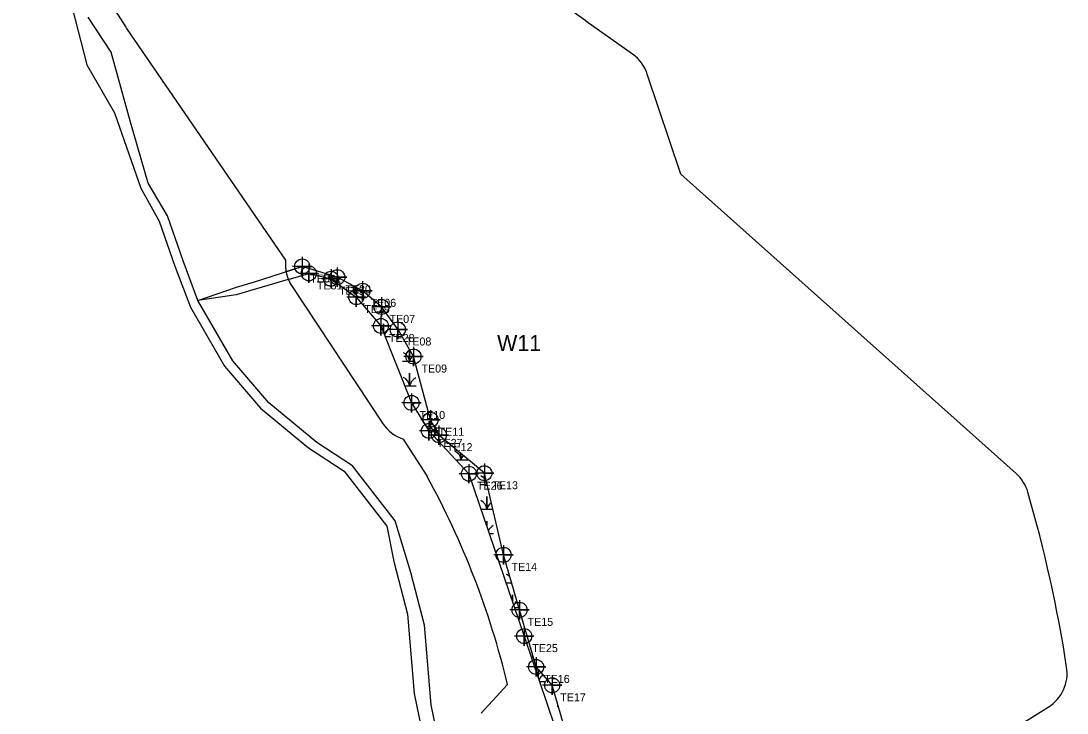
# Model space of a CAD drawing. Extents: x 1253697 to 1278588, y 912189 to 981699.
# Drawn here: x 1261524 to 1262831, y 929456 to 930320 of the extents above; entities that cross this region are included whole.
import ezdxf

# ---------------------------------------------------------------- set-up
doc = ezdxf.new("R2010")
doc.units = 0
for name, color, linetype in [('Default', 7, 'Continuous'), ('Exist Environmental Wetland Boundary', 7, 'Continuous'), ('Exist Environmental Wetland Boundary Cogo Comment', 7, 'Continuous'), ('Exist Environmental Wetland Boundary Cogo Number', 7, 'Continuous'), ('Exist Environmental Wetland Boundary Cogo Point CELL', 7, 'Continuous'), ('Exist Hydro Jurisdictional Stream or Body of Water Mitigable', 7, 'Continuous'), ('Exist Hydro Swamp or Marsh', 7, 'Continuous')]:
    doc.layers.add(name, color=color, linetype=linetype)

msp = doc.modelspace()

# ---------------------------------------------------------------- linework, layer by layer
at = {"layer": 'Default'}
for p, q in [((1261524.5, 930517.8), (1261655.6, 930312.4)), ((1261524.5, 930517.8), (1261655.6, 930312.4)), ((1261524.5, 930517.8), (1261655.6, 930312.4)), ((1261524.5, 930517.8), (1261655.6, 930312.4)), ((1262288.5, 930278.8), (1262230.3, 930320.2)), ((1262288.5, 930278.8), (1262230.3, 930320.2)), ((1262288.5, 930278.8), (1262230.3, 930320.2)), ((1262288.5, 930278.8), (1262230.3, 930320.2)), ((1261656.5, 930311), (1261855.1, 930021.6)), ((1261656.5, 930311), (1261855.1, 930021.6)), ((1261656.5, 930311), (1261855.1, 930021.6)), ((1261656.5, 930311), (1261855.1, 930021.6)), ((1261863.1, 929988.6), (1261976.2, 929817.7)), ((1261863.1, 929988.6), (1261976.2, 929817.7)), ((1261863.1, 929988.6), (1261976.2, 929817.7)), ((1261863.1, 929988.6), (1261976.2, 929817.7)), ((1262002.1, 929797.9), (1262031.6, 929751.8)), ((1262002.1, 929797.9), (1262031.6, 929751.8)), ((1262002.1, 929797.9), (1262031.6, 929751.8)), ((1262002.1, 929797.9), (1262031.6, 929751.8)), ((1262132.3, 929491.3), (1262099.5, 929455.5)), ((1262132.3, 929491.3), (1262099.5, 929455.5)), ((1262132.3, 929491.3), (1262099.5, 929455.5)), ((1262132.3, 929491.3), (1262099.5, 929455.5))]:
    msp.add_line(p, q, dxfattribs=at)
for points in [[(1262230.1, 930320.3), (1261823.6, 930606.2), (1261817.1, 930616.3), (1261806.6, 930645)], [(1262230.1, 930320.3), (1261823.6, 930606.2), (1261817.1, 930616.3), (1261806.6, 930645)], [(1262230.1, 930320.3), (1261823.6, 930606.2), (1261817.1, 930616.3), (1261806.6, 930645)], [(1262230.1, 930320.3), (1261823.6, 930606.2), (1261817.1, 930616.3), (1261806.6, 930645)], [(1262767.6, 929754.7), (1262349, 930128.9), (1262306.9, 930254)], [(1262767.6, 929754.7), (1262349, 930128.9), (1262306.9, 930254)], [(1262767.6, 929754.7), (1262349, 930128.9), (1262306.9, 930254)], [(1262767.6, 929754.7), (1262349, 930128.9), (1262306.9, 930254)], [(1262512, 929210.9), (1262495.3, 929268.1), (1262807.7, 929463)], [(1262512, 929210.9), (1262495.3, 929268.1), (1262807.7, 929463)], [(1262512, 929210.9), (1262495.3, 929268.1), (1262807.7, 929463)], [(1262512, 929210.9), (1262495.3, 929268.1), (1262807.7, 929463)]]:
    msp.add_lwpolyline(points, dxfattribs=at)
for centre, radius, start, end in [((1262201.4, 930279.4), 50, 54.5771, 54.8877), ((1262201.4, 930279.4), 50, 54.5771, 54.8877), ((1262201.4, 930279.4), 50, 54.5771, 54.8877), ((1262201.4, 930279.4), 50, 54.5771, 54.8877), ((1261697.7, 930339.3), 50, 212.5522, 214.4514), ((1261697.7, 930339.3), 50, 212.5522, 214.4514), ((1261697.7, 930339.3), 50, 212.5522, 214.4514), ((1261697.7, 930339.3), 50, 212.5522, 214.4514), ((1262259.5, 930238.1), 50, 18.5876, 54.5771), ((1262259.5, 930238.1), 50, 18.5876, 54.5771), ((1262259.5, 930238.1), 50, 18.5876, 54.5771), ((1262259.5, 930238.1), 50, 18.5876, 54.5771), ((1261904.8, 930016.2), 50, 173.8185, 213.5071), ((1261904.8, 930016.2), 50, 173.8185, 213.5071), ((1261904.8, 930016.2), 50, 173.8185, 213.5071), ((1261904.8, 930016.2), 50, 173.8185, 213.5071), ((1262017.9, 929845.3), 50, 213.5071, 251.5595), ((1262017.9, 929845.3), 50, 213.5071, 251.5595), ((1262017.9, 929845.3), 50, 213.5071, 251.5595), ((1262017.9, 929845.3), 50, 213.5071, 251.5595), ((1261111.3, 929246.3), 1050, 13.493, 28.7764), ((1261111.3, 929246.3), 1050, 13.493, 28.7764), ((1261111.3, 929246.3), 1050, 13.493, 28.7764), ((1261111.3, 929246.3), 1050, 13.493, 28.7764), ((1262734.3, 929717.5), 50, 16.1865, 48.2089), ((1262734.3, 929717.5), 50, 16.1865, 48.2089), ((1262734.3, 929717.5), 50, 16.1865, 48.2089), ((1262734.3, 929717.5), 50, 16.1865, 48.2089), ((1261111.3, 929246.3), 1740, 8.8188, 16.1865), ((1261111.3, 929246.3), 1740, 8.8188, 16.1865), ((1261111.3, 929246.3), 1740, 8.8188, 16.1865), ((1261111.3, 929246.3), 1740, 8.8188, 16.1865), ((1262781.3, 929505.4), 50, 301.9596, 8.8188), ((1262781.3, 929505.4), 50, 301.9596, 8.8188), ((1262781.3, 929505.4), 50, 301.9596, 8.8188), ((1262781.3, 929505.4), 50, 301.9596, 8.8188)]:
    msp.add_arc(centre, radius, start, end, dxfattribs=at)
at = {"layer": 'Exist Environmental Wetland Boundary'}
for points in [[(1261858.5, 929997.3), (1261793.3, 929978), (1261745.3, 929971.2), (1261793.9, 929987.8), (1261814.8, 929993.8), (1261875.9, 930013.5)], [(1262206.1, 929428.6), (1262188.1, 929490.2), (1262168, 929513.4), (1262147.3, 929584.5), (1262127.3, 929653.2), (1262103.4, 929755.2), (1262046.6, 929802.8), (1262036.2, 929822), (1262014.8, 929901), (1261996.2, 929934.1), (1261974.9, 929963), (1261951.3, 929983.1), (1261919.7, 930000.1), (1261875.9, 930013.5), (1261855.6, 930007)], [(1261858.5, 929997.3), (1261884.2, 930004.9), (1261911.9, 929998.1), (1261943.4, 929975.2), (1261974.2, 929939.2), (1262012.4, 929843), (1262034.2, 929808.1), (1262084.1, 929754.6), (1262153.2, 929551.7), (1262191.5, 929438.5)]]:
    msp.add_lwpolyline(points, dxfattribs=at)
at = {"layer": 'Exist Environmental Wetland Boundary Cogo Point CELL'}
for points in [[(1261875.9, 930025.5), (1261875.9, 930001.5), (1261875.9, 930013.5), (1261887.9, 930013.5), (1261863.9, 930013.5)], [(1261884.2, 930016.9), (1261884.2, 929992.9), (1261884.2, 930004.9), (1261896.2, 930004.9), (1261872.2, 930004.9)], [(1261911.9, 930010.1), (1261911.9, 929986.1), (1261911.9, 929998.1), (1261923.9, 929998.1), (1261899.9, 929998.1)], [(1261919.7, 930012.1), (1261919.7, 929988.1), (1261919.7, 930000.1), (1261931.7, 930000.1), (1261907.7, 930000.1)], [(1261951.3, 929995.1), (1261951.3, 929971.1), (1261951.3, 929983.1), (1261963.3, 929983.1), (1261939.3, 929983.1)], [(1261943.4, 929987.2), (1261943.4, 929963.2), (1261943.4, 929975.2), (1261955.4, 929975.2), (1261931.4, 929975.2)], [(1261974.9, 929975), (1261974.9, 929951), (1261974.9, 929963), (1261986.9, 929963), (1261962.9, 929963)], [(1261974.2, 929951.2), (1261974.2, 929927.2), (1261974.2, 929939.2), (1261986.2, 929939.2), (1261962.2, 929939.2)], [(1261995.2, 929946.8), (1261995.2, 929922.8), (1261995.2, 929934.8), (1262007.2, 929934.8), (1261983.2, 929934.8)], [(1262014.8, 929913), (1262014.8, 929889), (1262014.8, 929901), (1262026.8, 929901), (1262002.8, 929901)], [(1262012.4, 929855), (1262012.4, 929831), (1262012.4, 929843), (1262024.4, 929843), (1262000.4, 929843)], [(1262036.2, 929834), (1262036.2, 929810), (1262036.2, 929822), (1262048.2, 929822), (1262024.2, 929822)], [(1262034.2, 929820.1), (1262034.2, 929796.1), (1262034.2, 929808.1), (1262046.2, 929808.1), (1262022.2, 929808.1)], [(1262046.6, 929814.8), (1262046.6, 929790.8), (1262046.6, 929802.8), (1262058.6, 929802.8), (1262034.6, 929802.8)], [(1262084.1, 929766.6), (1262084.1, 929742.6), (1262084.1, 929754.6), (1262096.1, 929754.6), (1262072.1, 929754.6)], [(1262103.4, 929767.2), (1262103.4, 929743.2), (1262103.4, 929755.2), (1262115.4, 929755.2), (1262091.4, 929755.2)], [(1262127.3, 929665.2), (1262127.3, 929641.2), (1262127.3, 929653.2), (1262139.3, 929653.2), (1262115.3, 929653.2)], [(1262147.3, 929596.5), (1262147.3, 929572.5), (1262147.3, 929584.5), (1262159.3, 929584.5), (1262135.3, 929584.5)], [(1262153.2, 929563.7), (1262153.2, 929539.7), (1262153.2, 929551.7), (1262165.2, 929551.7), (1262141.2, 929551.7)], [(1262168, 929525.2), (1262168, 929501.2), (1262168, 929513.2), (1262180, 929513.2), (1262156, 929513.2)], [(1262188.1, 929502.3), (1262188.1, 929478.3), (1262188.1, 929490.2), (1262200.1, 929490.2), (1262176.1, 929490.2)]]:
    msp.add_lwpolyline(points, dxfattribs=at)
for centre in [(1261875.9, 930013.5), (1261884.2, 930004.9), (1261911.9, 929998.1), (1261919.7, 930000.1), (1261943.4, 929975.2), (1261951.3, 929983.1), (1261974.9, 929963), (1261974.2, 929939.2), (1261995.2, 929934.8), (1262014.8, 929901), (1262012.4, 929843), (1262036.2, 929822), (1262034.2, 929808.1), (1262046.6, 929802.8), (1262084.1, 929754.6), (1262103.4, 929755.2), (1262127.3, 929653.2), (1262147.3, 929584.5), (1262153.2, 929551.7), (1262168, 929513.2), (1262188.1, 929490.2)]:
    msp.add_circle(centre, 9.38, dxfattribs=at)
at = {"layer": 'Exist Hydro Jurisdictional Stream or Body of Water Mitigable'}
for points in [[(1261588.5, 930336.7), (1261606.8, 930265.5), (1261641.3, 930205.5), (1261674.2, 930111.4), (1261697.3, 930070.1), (1261716.9, 930014), (1261736.5, 929962.7), (1261778.8, 929888.8), (1261823.7, 929836.4), (1261883.7, 929787), (1261928.3, 929757.7), (1261981.4, 929689.1), (1261990.4, 929645), (1262007.3, 929579.2), (1262015.8, 929479.9), (1262035, 929386.7)], [(1262056.2, 929372.7), (1262037, 929465.9), (1262028.5, 929565.2), (1262011.6, 929631), (1261991.8, 929695.9), (1261938.6, 929764.5), (1261894, 929793.8), (1261834, 929843.2), (1261789.1, 929895.5), (1261745.3, 929971.2), (1261727.2, 930020.7), (1261707.7, 930076.9), (1261683.4, 930117.5), (1261661.4, 930193.9), (1261637.2, 930281.1), (1261608.6, 930325.1)], [(1261697.3, 930070.1), (1261716.9, 930014), (1261736.5, 929962.7), (1261778.8, 929888.8), (1261823.7, 929836.4), (1261883.7, 929787), (1261928.3, 929757.7), (1261981.4, 929689.1)]]:
    msp.add_lwpolyline(points, dxfattribs=at)
at = {"layer": 'Exist Hydro Swamp or Marsh'}
for p, q in [((1261913.2, 929997.2), (1261913.2, 930002.1)), ((1261913.2, 930002.1), (1261913.2, 929997.2)), ((1261936.8, 929987.5), (1261943, 929987.5)), ((1261979.5, 929925.9), (1261986.2, 929925.9)), ((1262018.3, 929833.6), (1262018.4, 929833.6)), ((1262109.7, 929679.7), (1262115, 929679.7)), ((1262130.6, 929618.1), (1262137.5, 929618.1)), ((1262141.1, 929587.4), (1262146.4, 929587.4)), ((1262162.2, 929525.8), (1262164.4, 929525.8)), ((1262170.8, 929499.9), (1262170.8, 929510.2)), ((1262170.8, 929510.2), (1262170.8, 929499.9)), ((1262172.4, 929495), (1262179.4, 929495)), ((1262194.4, 929464.2), (1262195.7, 929464.2))]:
    msp.add_line(p, q, dxfattribs=at)
for points in [[(1261969, 929956.7), (1261977.6, 929956.7), (1261977.6, 929959.4)], [(1261977.6, 929959.4), (1261977.6, 929956.7), (1261979.5, 929956.7)], [(1261977.6, 929930.8), (1261977.6, 929941.7), (1261977.6, 929930.8)], [(1262001.2, 929895.2), (1262009.8, 929895.2), (1262009.8, 929910)], [(1262009.8, 929910), (1262009.8, 929895.2), (1262016.4, 929895.2)], [(1262003.9, 929864.4), (1262009.8, 929864.4), (1262009.8, 929880.2), (1262009.8, 929864.4), (1262018.4, 929864.4)], [(1262039.1, 929802.8), (1262042, 929802.8), (1262042, 929811.2)], [(1262042, 929811.2), (1262042, 929802.8), (1262046.5, 929802.8)], [(1262067.9, 929772), (1262074.2, 929772), (1262074.2, 929779.6)], [(1262074.2, 929779.6), (1262074.2, 929772), (1262082.8, 929772)], [(1262097.8, 929741.3), (1262106.4, 929741.3), (1262106.4, 929742.7)], [(1262106.4, 929742.7), (1262106.4, 929741.3), (1262106.7, 929741.3)], [(1262099.2, 929710.5), (1262106.4, 929710.5), (1262106.4, 929726.3), (1262106.4, 929710.5), (1262113.9, 929710.5)], [(1262106.4, 929689.3), (1262106.4, 929695.5), (1262106.4, 929689.3)], [(1262138.6, 929594.8), (1262138.6, 929603.1), (1262138.6, 929594.8)]]:
    msp.add_lwpolyline(points, dxfattribs=at)
for centre, radius, start, end in [((1261931.4, 929981.4), 19.2, 122.1274, 138.0669), ((1261963.6, 929950.7), 19.2, 122.1274, 128.8087), ((1261965.3, 929955.8), 12.3, 4.1403, 23.9295), ((1261995.8, 929950.7), 19.2, 155.9568, 161.6222), ((1261995.8, 929919.9), 19.2, 122.1274, 153.9329), ((1261997.5, 929894.3), 12.3, 4.1403, 67.535), ((1262028, 929889.1), 19.2, 136.3951, 161.6222), ((1261997.5, 929863.5), 12.3, 4.1403, 67.535), ((1262028, 929858.3), 19.2, 122.1274, 161.6222), ((1262028, 929827.5), 19.2, 122.1274, 137.1567), ((1262029.7, 929801.9), 12.3, 4.1403, 67.535), ((1262060.2, 929796.8), 19.2, 146.8812, 161.6222), ((1262061.9, 929771.2), 12.3, 4.1403, 67.535), ((1262092.4, 929766), 19.2, 143.7396, 161.6222), ((1262094.1, 929740.4), 12.3, 4.1403, 67.535), ((1262124.6, 929735.2), 19.2, 159.8505, 161.6222), ((1262094.1, 929709.6), 12.3, 4.1403, 67.535), ((1262124.6, 929704.4), 19.2, 131.2337, 161.6222), ((1262124.6, 929673.6), 19.2, 122.1274, 148.2497), ((1262126.3, 929617.3), 12.3, 42.8177, 67.535), ((1262156.8, 929581.3), 19.2, 131.7481, 151.0529), ((1262189, 929489), 19.2, 130.5314, 154.5034)]:
    msp.add_arc(centre, radius, start, end, dxfattribs=at)

# ---------------------------------------------------------------- texts
at = {"layer": 'Exist Environmental Wetland Boundary Cogo Comment'}
for s, p in [('TE04', (1261885.9, 929993.5)), ('TE31', (1261894.2, 929984.9)), ('TE05', (1261921.9, 929978.1)), ('TE30', (1261929.7, 929980.1)), ('TE06', (1261961.3, 929963.1)), ('TE29', (1261953.4, 929955.2)), ('TE07', (1261984.9, 929943)), ('TE28', (1261984.2, 929919.2)), ('TE08', (1262005.2, 929914.8)), ('TE09', (1262024.8, 929881)), ('TE10', (1262022.4, 929823)), ('TE11', (1262046.2, 929802)), ('TE27', (1262044.2, 929788.1)), ('TE12', (1262056.6, 929782.8)), ('TE26', (1262094.1, 929734.6)), ('TE13', (1262113.4, 929735.2)), ('TE14', (1262137.3, 929633.2)), ('TE15', (1262157.3, 929564.5)), ('TE25', (1262163.2, 929531.7)), ('TE16', (1262178, 929493.2)), ('TE17', (1262198.1, 929470.2))]:
    msp.add_text(s, height=10, dxfattribs=at).set_placement(p)
at = {"layer": 'Exist Environmental Wetland Boundary Cogo Number'}
msp.add_text('W11', height=20, dxfattribs=at).set_placement((1262119.3, 929907.9))

doc.saveas('drawing.dxf')
